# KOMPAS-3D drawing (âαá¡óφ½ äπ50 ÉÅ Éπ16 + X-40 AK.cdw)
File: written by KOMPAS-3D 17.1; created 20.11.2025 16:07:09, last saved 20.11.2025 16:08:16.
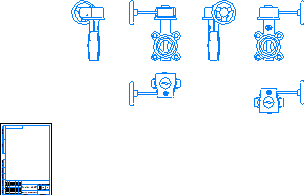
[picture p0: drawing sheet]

Sheet 1: A4, portrait

Title block, sheet 1: name: Гранвэл Ду50; material: Сталь 10  ГОСТ 1050-88; mass: 6,47; sheets: 1; sheet format: A4

Views: Вид 1, Спереди, Проекционный вид 2, Проекционный вид 3, Проекционный вид 4, Проекционный вид 5, Проекционный вид 6
Referenced files in \\adlc.lan\data\АДЛ_ПКД\3D-модели\ADL production\Дисковые поворотные затворы ГРАНВЭЛ\с резьбовыми проушинами с китайским редуктором Ру 16\KOMPAS 3D\: Гранвэл Ду50 РП Ру16 + X-40 AK.m3d
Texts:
  Andrey
  АДЛ
Dimensions and other numbers on the sheet: 1:1; 1; 6,47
